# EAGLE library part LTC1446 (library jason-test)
Dual DAC
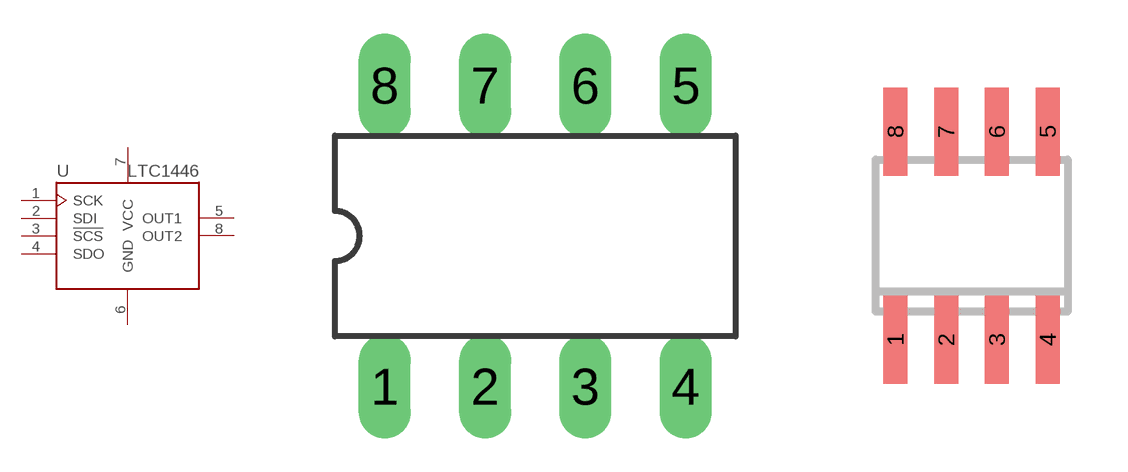
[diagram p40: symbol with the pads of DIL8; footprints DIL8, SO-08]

Designator prefix -

## LTC1446CN8  [DIL8]
1  SCK  in
2  SDI  in
3  !SCS  in
4  SDO
5  OUT1  out
6  GND  pwr
7  VCC  pwr
8  OUT2  out

## LTC1446CS8  [SO-08]
Pads as for DIL8

## Footprint DIL8 (pad centres in mm)
Dual In Line package type P
drill 0.813 long: 1 -3.81,-3.81; 2 -1.27,-3.81; 3 1.27,-3.81; 4 3.81,-3.81; 5 3.81,3.81; 6 1.27,3.81; 7 -1.27,3.81; 8 -3.81,3.81

## Footprint SO-08 (pad centres in mm)
Small Outline Narrow Plastic Gull Wing 150-mil body, package type SN
smd 0.6 x 2.2: 1 -1.905,-2.6; 2 -0.635,-2.6; 3 0.635,-2.6; 4 1.905,-2.6; 5 1.905,2.6; 6 0.635,2.6; 7 -0.635,2.6; 8 -1.905,2.6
